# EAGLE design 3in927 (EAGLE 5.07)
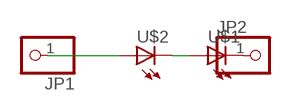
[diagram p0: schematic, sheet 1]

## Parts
JP1  PINHD-1X11X0.4  [1X01]
JP2  PINHD-1X11X0.4  [1X01]
U$1  LEDSMT1206  [1206]
U$2  LEDSMT1206  [1206]

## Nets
N$1: JP1.1 U$2.A
N$3: U$1.A U$2.C
N$4: JP2.1 U$1.C

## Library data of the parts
JP1 JP2 = pinhead:PINHD-1X1: PIN HEADER
U$1 U$2 = led(2):LED: LED

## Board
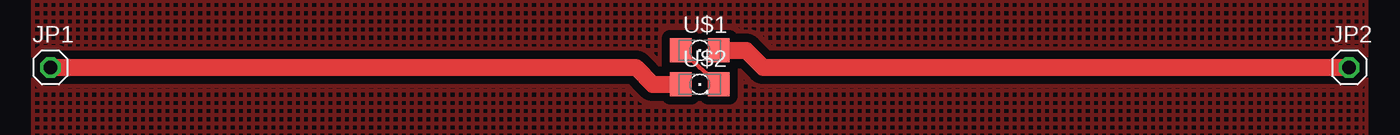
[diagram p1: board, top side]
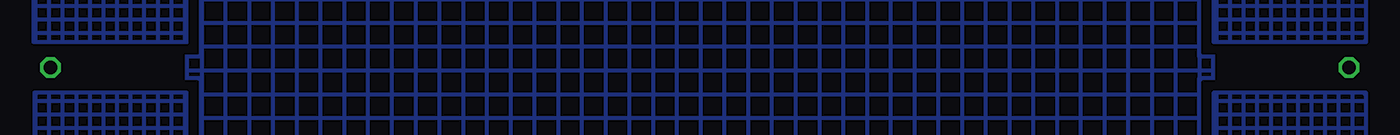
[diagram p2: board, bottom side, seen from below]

No outline drawn. Coordinates in mm, seen from the top.
Copper layers (1*16): Top 0.035mm / dielectric 1.5mm / Bottom 0.035mm
Design rules "default": minimum track width 10mil, minimum drill 24mil, track to track 8mil, track to pad 8mil, pad to pad 8mil, via to via 8mil, smd to smd 8mil, copper to edge 40mil, drill to drill 8mil, minimum pad ring 10mil, minimum via ring 8mil, stop-mask expansion 4mil, vias tented up to drill 0mil, thermal gap 10mil

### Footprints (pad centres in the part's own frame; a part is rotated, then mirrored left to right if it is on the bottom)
1X01 = drill 1.016 octagon: 1 0,0
1206 = smd 1.6 x 1.803: A -1.422,0; C 1.422,0

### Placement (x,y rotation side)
JP1  1.27,12.7 0 top
JP2  98.48,12.7 0 top
U$1  49.87,13.97 0 top
U$2  49.87,11.43 0 top

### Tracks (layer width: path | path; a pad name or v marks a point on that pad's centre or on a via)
N$1
  Top 1.27: JP1.1 45.09,12.7 46.35,11.43 U$2.A
N$2
  pour Top (isolate 0.61, hatched): 0,25.4 99.75,25.4 99.75,0 0,0
  pour Bottom (isolate 0.813, rank 2, hatched): 11.43,25.4 88.27,25.4 88.27,0 11.43,0
N$3
  Top 0.305: U$2.C 49.85,12.7 U$1.A
N$4
  Top 1.27: JP2.1 54.61,12.7 53.34,13.97 U$1.C
N$5
  pour Bottom (hatched): 0,25.4 11.43,25.4 11.43,14.61 0,14.61
  pour Bottom (hatched): 0,10.79 11.43,10.79 11.43,0 0,0
  pour Bottom (hatched): 88.27,10.79 99.69,10.79 99.69,0 88.27,0
  pour Bottom (hatched): 88.27,25.4 99.75,25.4 99.75,14.61 88.27,14.61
